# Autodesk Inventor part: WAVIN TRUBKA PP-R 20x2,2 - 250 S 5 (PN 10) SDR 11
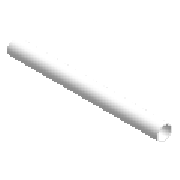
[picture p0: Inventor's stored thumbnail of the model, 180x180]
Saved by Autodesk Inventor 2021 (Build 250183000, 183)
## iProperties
IsCustomPart: 1
Created: 2020-06
Part Number: WAVIN TRUBKA PP-R 20x2,2 - 250 S 5 (PN 10) SDR 11
Material: PVC, nepoplastované
Description: Rozvody studené (pitné) vody, teplé vody a vytápění (standardní, I.)
Document SubType Name: Modeling
Standard: WAVIN_STANDARD
Designer: naus
Standard Revision: 2020-06
Manufacturer: WAVIN
Standards Organization: WAVIN_ST_ORG
Language: cs-CZ
Size Designation: 20x2,2 - 250
Categories: <MemberInstance><Categories><Category DisplayName="Trubky a potrubí" InternalName="4347fa0f-2144-441d-94cd-e3e15c92b736" Mnemonic="TUBEANDPIPE"><CategoryParamet
Stock Number: WAVIN TRUBKA 20x2,2
Mass: 39.6755 g
Surface Area: 282.062 cm^2
Volume: 30.7562 cm^3
Density: 1.29 g/cm^3
Appearance: Hladká – bílá
NAME: PIPING: DIN 8062 Pipe
DATA: <meta><inlinegroups number="1" deflen="25"></inlinegroups><connections number="2"></connections><angles><a>3.14159265358979</a></angles></meta>
L: 250.000 mm
PL: 250
Vnejsi_Plocha: 0,016 m^2
Volume_Fluid_Category: YES
Volume_Fluid: 4778362,426 mm^3
Author: naus
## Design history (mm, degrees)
sketch "Sketch1"
  geometry: C1 r 10 at (0, 0); C2 r 7.8 at (0, 0); 1 further point
  constraints: 2 centre point, 2 coincident, 1 concentric
  dimensions: "d0" = 20 diameter of C1 (= OD); "d1" = 2.2 radial gap between concentric circles of C1 C2 (= t)
extrude "Extrusion1" new body sketch "Sketch1" distance "d2" = 250 (= L); taper "d3" = 0 deg
workaxis "Work Axis1"
workaxis "Work Axis2"
workpoint "Work Point1"
workaxis "Work Axis3"
workpoint "Work Point2"
node "End"
node "Middle"
node "Tangent1"
body "Solid1"
other parameters: "OD" = 20 [user parameter; used in 2 equation terms], "t" = 2.2 [user parameter; used in 1 equation term], "L" = 250 (= PL) [user parameter; used in 3 equation terms], "ID" = 15.6 [user parameter; used in 1 equation term], "Size_Designation" = 12.345 [user parameter], "d5" = 125 (= 0.5 x PL), "Volume_Fluid" = 47783.62426 (computed from ID, L) [user parameter], "Vnejsi_Plocha" = 1570.79633 (computed from OD, L) [user parameter]
